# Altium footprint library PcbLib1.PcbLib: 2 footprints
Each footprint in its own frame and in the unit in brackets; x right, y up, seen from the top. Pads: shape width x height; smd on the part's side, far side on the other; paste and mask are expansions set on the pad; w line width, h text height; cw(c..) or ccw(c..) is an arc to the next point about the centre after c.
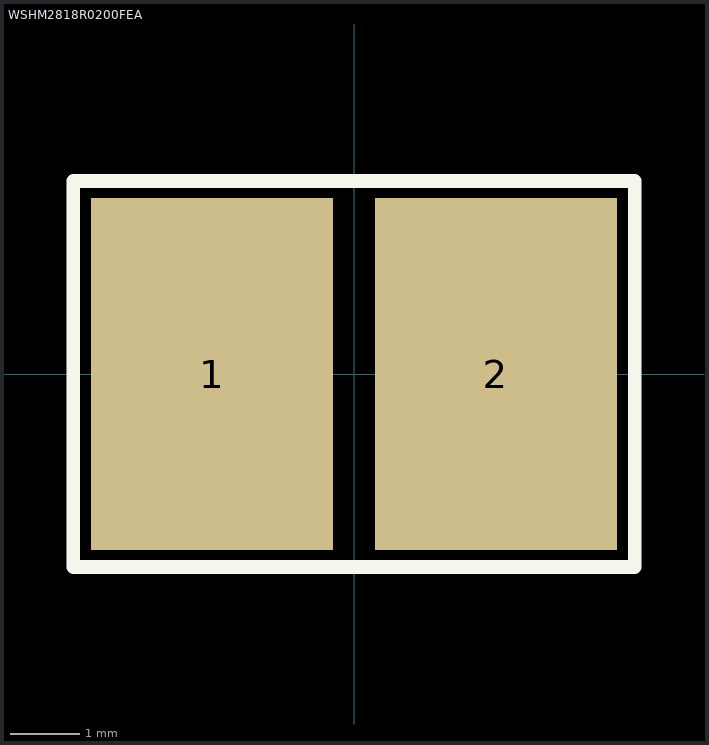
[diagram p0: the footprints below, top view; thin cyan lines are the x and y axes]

## PCBComponent_1 [mm]

## WSHM2818R0200FEA [mm]
pads (2):
  rect 3.5x5.1 smd: 1(-2.055,0) 2(2.055,0)
Top Overlay:
  lines w0.2: -4.064,-2.794 4.064,-2.794 4.064,2.794 -4.064,2.794 -4.064,-0.309 -4.064,-2.794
